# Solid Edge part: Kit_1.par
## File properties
Sűrűség: 0,000 kg/m^3
Pontosság: 0,990
Author: bmolnar
Last saved by: bmolnar
Revision: 77
Username: bmolnar
Dokumentum tartalom típus: 0
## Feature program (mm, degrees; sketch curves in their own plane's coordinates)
base feature "unnamed BaseFeature 1"
sketch for "unnamed Cutout 1" plane through (0, 0.0012, 83.3) normal (0, 0, -1) x-axis (-1, 0, 0)
  circle centre (0, -0.0012) radius 8
extrude "unnamed Cutout 1" cut through along -normal
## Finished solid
Body 1: solid body, 48 faces, 65 edges, 51 vertices, 1 internal void.
  Faces by surface: cone 16, cylinder 16, plane 12, torus 4
  Edges by curve: circle 51, line 14
Bounding box of the edges (mm; curved faces can reach further): 55.000 x 54.575 x 12.300, from (-27.5, -25.9, 83.3) to (27.5, 28.675, 95.6).
Cylindrical faces by radius (mm): R1.25 x2, R2.5 x4, R8 x1, R8.27 x1, R8.85 x1, R9 x1, R10.16 x1, R10.25 x1, R17 x1, R23.975 x1, R25.9 x1, R27.5 x1
Conical faces (half-angle, radius in mm at the cone's reference point): 3 deg R10.205 x1, 7 deg R9.5925 x1, 14 deg R8.135 x1, 14 deg R8.4811 x1, 17 deg R8.135 x1, 23 deg R8.829 x1, 42.5 deg R8.1233 x1, 45 deg R9.1 x2, 45 deg R16.5 x1, 45 deg R25.8 x2, 84 deg R76.3675 x2, 85 deg R9.9463 x1, 87 deg R8.1765 x1
Toroidal faces (ring radius, tube radius in mm): R8.8057 r0.2025 x1, R9.2522 r0.2925 x1, R9.96 r0.2 x1, R17.8 r0.8 x1
Planar faces by outward normal: +z 7, -z 3, oblique 2
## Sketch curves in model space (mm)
circle centre (0, 0, 83.3) radius 8
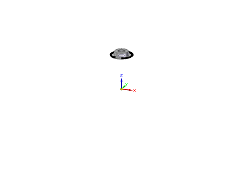
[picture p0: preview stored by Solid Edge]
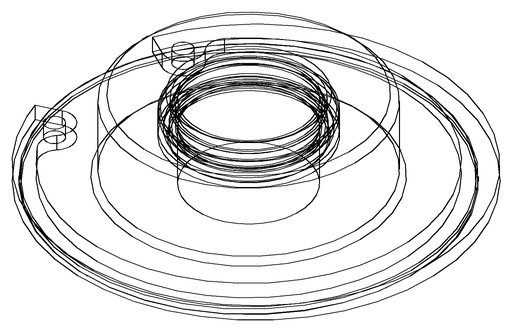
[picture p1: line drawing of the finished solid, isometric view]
